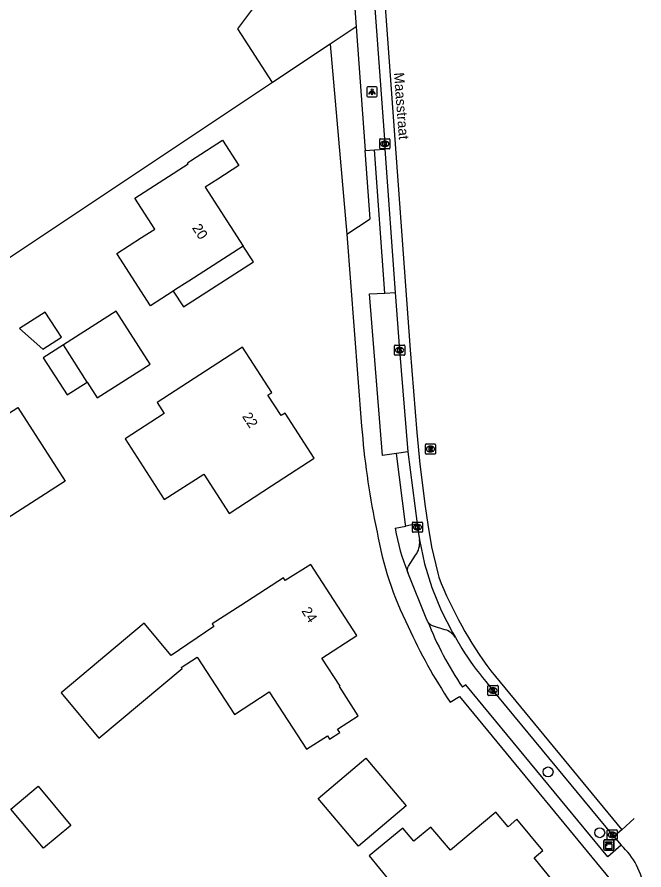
# Model space of a CAD drawing. Extents: x 156651 to 158072, y 387631 to 388990.
# Drawn here: x 157592.7 to 157654.4, y 387966 to 388049.9 of the extents above; entities that cross this region are included whole.
import ezdxf

# ---------------------------------------------------------------- set-up
doc = ezdxf.new("R2010")
doc.units = 0
for name, color, linetype in [('IMGEO_Boom', 7, 'Continuous'), ('IMGEO_Gemengd_bos', 7, 'Continuous'), ('IMGEO_Grasland_overig', 7, 'Continuous'), ('IMGEO_Kast', 7, 'Continuous'), ('IMGEO_Kolk', 7, 'Continuous'), ('IMGEO_Lichtpunt', 7, 'Continuous'), ('IMGEO_Openbare_ruimte_label', 7, 'Continuous'), ('IMGEO_Pand', 7, 'Continuous'), ('IMGEO_Pand_nummerreeks', 7, 'Continuous'), ('IMGEO_Pand_overbouw', 7, 'Continuous'), ('IMGEO_Pand_vergunning_verleend', 7, 'Continuous'), ('IMGEO_Rijbaan_lokaal_open', 7, 'Continuous'), ('IMGEO_Rioolput', 7, 'Continuous'), ('IMGEO_Voetpad_open', 7, 'Continuous')]:
    doc.layers.add(name, color=color, linetype=linetype)

msp = doc.modelspace()

# ---------------------------------------------------------------- linework, layer by layer
at = {"layer": 'IMGEO_Boom'}
for centre in [(157644.934, 387975.668), (157650.013, 387969.688)]:
    msp.add_circle(centre, 0.489, dxfattribs=at)
at = {"layer": 'IMGEO_Gemengd_bos'}
for points in [[(157617.824, 388043.477), (157568.335, 388010.487), (157551.976, 388000), (157551.233, 387999.524), (157548.86, 387998.003), (157547.263, 388000), (157521.408, 388032.33), (157543.243, 388052.841), (157602.721, 388107.759)], [(157617.824, 388043.477), (157614.435, 388048.767), (157619.655, 388055.738), (157620.91, 388056.517), (157620.87, 388061.577), (157622.996, 388063.579), (157624.989, 388063.89)], [(157626.073, 388048.976), (157623.5, 388047.261)], [(157623.5, 388047.261), (157617.824, 388043.477)]]:
    msp.add_lwpolyline(points, dxfattribs=at)
at = {"layer": 'IMGEO_Grasland_overig'}
msp.add_lwpolyline([(157623.5, 388047.261), (157625.156, 388028.557)], dxfattribs=at)
at = {"layer": 'IMGEO_Kast'}
for p, q in [((157650.416, 387968.061), (157650.416, 387968.902)), ((157650.416, 387968.902), (157650.416, 387968.061)), ((157650.491, 387968.986), (157651.332, 387968.986)), ((157651.332, 387968.986), (157650.491, 387968.986)), ((157651.416, 387968.911), (157651.416, 387968.07)), ((157651.416, 387968.07), (157651.416, 387968.911)), ((157651.341, 387967.986), (157650.5, 387967.986)), ((157650.5, 387967.986), (157651.341, 387967.986))]:
    msp.add_line(p, q, dxfattribs=at)
for points in [[(157650.611, 387968.776), (157651.211, 387968.776), (157651.211, 387968.691), (157650.611, 387968.691), (157650.611, 387968.776)], [(157650.611, 387968.601), (157651.211, 387968.601), (157651.211, 387968.112), (157650.611, 387968.112), (157650.611, 387968.601)]]:
    msp.add_lwpolyline(points, dxfattribs=at)
msp.add_circle((157650.695, 387968.45), 0.0377, dxfattribs=at)
for centre, start, end in [((157650.494, 387968.908), 92.4484, 184.28452), ((157650.494, 387968.908), 92.4484, 184.28452), ((157651.338, 387968.908), 2.4484, 94.28452), ((157651.338, 387968.908), 2.4484, 94.28452), ((157650.494, 387968.064), 182.4484, 274.28452), ((157650.494, 387968.064), 182.4484, 274.28452), ((157651.338, 387968.064), 272.4484, 4.28452), ((157651.338, 387968.064), 272.4484, 4.28452)]:
    msp.add_arc(centre, 0.0779, start, end, dxfattribs=at)
at = {"layer": 'IMGEO_Kolk'}
for p, q in [((157628.378, 388037.026), (157628.378, 388037.878)), ((157628.453, 388037.952), (157629.305, 388037.952)), ((157628.866, 388037.732), (157628.891, 388037.732)), ((157629.379, 388037.878), (157629.379, 388037.026)), ((157629.305, 388036.952), (157628.453, 388036.952)), ((157628.889, 388037.172), (157628.864, 388037.172)), ((157629.833, 388016.732), (157629.833, 388017.584)), ((157629.908, 388017.658), (157630.76, 388017.658)), ((157630.321, 388017.438), (157630.346, 388017.438)), ((157630.834, 388017.584), (157630.834, 388016.732)), ((157630.76, 388016.658), (157629.908, 388016.658)), ((157630.344, 388016.878), (157630.319, 388016.878)), ((157631.587, 387999.317), (157631.587, 388000.169)), ((157631.662, 388000.243), (157632.514, 388000.243)), ((157632.098, 387999.463), (157632.073, 387999.463)), ((157632.075, 388000.023), (157632.1, 388000.023)), ((157632.588, 388000.169), (157632.588, 387999.317)), ((157632.514, 387999.243), (157631.662, 387999.243)), ((157639.012, 387983.254), (157639.012, 387984.106)), ((157639.087, 387984.18), (157639.939, 387984.18)), ((157639.5, 387983.96), (157639.525, 387983.96)), ((157640.013, 387984.106), (157640.013, 387983.254)), ((157639.939, 387983.18), (157639.087, 387983.18)), ((157639.523, 387983.4), (157639.498, 387983.4)), ((157650.742, 387969.051), (157650.742, 387969.903)), ((157650.817, 387969.977), (157651.669, 387969.977)), ((157651.23, 387969.757), (157651.255, 387969.757)), ((157651.743, 387969.903), (157651.743, 387969.051)), ((157651.669, 387968.977), (157650.817, 387968.977)), ((157651.253, 387969.197), (157651.228, 387969.197))]:
    msp.add_line(p, q, dxfattribs=at)
for points in [[(157628.378, 388037.026), (157628.378, 388037.878)], [(157628.453, 388037.952), (157629.305, 388037.952)], [(157628.699, 388037.652), (157628.822, 388037.652), (157628.822, 388037.501), (157628.952, 388037.652), (157629.116, 388037.652), (157628.97, 388037.501), (157629.123, 388037.252), (157628.971, 388037.252), (157628.886, 388037.416), (157628.822, 388037.349), (157628.822, 388037.252), (157628.699, 388037.252), (157628.699, 388037.652)], [(157629.379, 388037.878), (157629.379, 388037.026)], [(157629.305, 388036.952), (157628.453, 388036.952)], [(157629.833, 388016.732), (157629.833, 388017.584)], [(157629.908, 388017.658), (157630.76, 388017.658)], [(157630.154, 388017.358), (157630.277, 388017.358), (157630.277, 388017.207), (157630.407, 388017.358), (157630.571, 388017.358), (157630.425, 388017.207), (157630.578, 388016.958), (157630.426, 388016.958), (157630.341, 388017.122), (157630.277, 388017.055), (157630.277, 388016.958), (157630.154, 388016.958), (157630.154, 388017.358)], [(157630.834, 388017.584), (157630.834, 388016.732)], [(157630.76, 388016.658), (157629.908, 388016.658)], [(157631.587, 387999.317), (157631.587, 388000.169)], [(157631.662, 388000.243), (157632.514, 388000.243)], [(157631.908, 387999.943), (157632.031, 387999.943), (157632.031, 387999.792), (157632.161, 387999.943), (157632.325, 387999.943), (157632.179, 387999.792), (157632.332, 387999.543), (157632.18, 387999.543), (157632.095, 387999.707), (157632.031, 387999.64), (157632.031, 387999.543), (157631.908, 387999.543), (157631.908, 387999.943)], [(157632.588, 388000.169), (157632.588, 387999.317)], [(157632.514, 387999.243), (157631.662, 387999.243)], [(157639.012, 387983.254), (157639.012, 387984.106)], [(157639.087, 387984.18), (157639.939, 387984.18)], [(157639.333, 387983.88), (157639.456, 387983.88), (157639.456, 387983.729), (157639.586, 387983.88), (157639.75, 387983.88), (157639.604, 387983.729), (157639.757, 387983.48), (157639.605, 387983.48), (157639.52, 387983.644), (157639.456, 387983.577), (157639.456, 387983.48), (157639.333, 387983.48), (157639.333, 387983.88)], [(157640.013, 387984.106), (157640.013, 387983.254)], [(157639.939, 387983.18), (157639.087, 387983.18)], [(157650.742, 387969.051), (157650.742, 387969.903)], [(157650.817, 387969.977), (157651.669, 387969.977)], [(157651.063, 387969.677), (157651.186, 387969.677), (157651.186, 387969.526), (157651.316, 387969.677), (157651.48, 387969.677), (157651.334, 387969.526), (157651.487, 387969.277), (157651.335, 387969.277), (157651.25, 387969.441), (157651.186, 387969.374), (157651.186, 387969.277), (157651.063, 387969.277), (157651.063, 387969.677)], [(157651.743, 387969.903), (157651.743, 387969.051)], [(157651.669, 387968.977), (157650.817, 387968.977)]]:
    msp.add_lwpolyline(points, dxfattribs=at)
for centre, start, end in [((157628.455, 388037.876), 91.55205, 178.44795), ((157628.455, 388037.876), 91.55205, 178.44795), ((157629.303, 388037.876), 1.55205, 88.44795), ((157629.303, 388037.876), 1.55205, 88.44795), ((157628.455, 388037.028), 181.55205, 268.44795), ((157628.455, 388037.028), 181.55205, 268.44795), ((157629.303, 388037.028), 271.55205, 358.44795), ((157629.303, 388037.028), 271.55205, 358.44795), ((157629.91, 388017.582), 91.55205, 178.44795), ((157629.91, 388017.582), 91.55205, 178.44795), ((157630.758, 388017.582), 1.55205, 88.44795), ((157630.758, 388017.582), 1.55205, 88.44795), ((157629.91, 388016.734), 181.55205, 268.44795), ((157629.91, 388016.734), 181.55205, 268.44795), ((157630.758, 388016.734), 271.55205, 358.44795), ((157630.758, 388016.734), 271.55205, 358.44795), ((157631.664, 388000.167), 91.55205, 178.44795), ((157631.664, 388000.167), 91.55205, 178.44795), ((157632.512, 388000.167), 1.55205, 88.44795), ((157632.512, 388000.167), 1.55205, 88.44795), ((157631.664, 387999.319), 181.55205, 268.44795), ((157631.664, 387999.319), 181.55205, 268.44795), ((157632.512, 387999.319), 271.55205, 358.44795), ((157632.512, 387999.319), 271.55205, 358.44795), ((157639.089, 387984.104), 91.55205, 178.44795), ((157639.089, 387984.104), 91.55205, 178.44795), ((157639.937, 387984.104), 1.55205, 88.44795), ((157639.937, 387984.104), 1.55205, 88.44795), ((157639.089, 387983.256), 181.55205, 268.44795), ((157639.089, 387983.256), 181.55205, 268.44795), ((157639.937, 387983.256), 271.55205, 358.44795), ((157639.937, 387983.256), 271.55205, 358.44795), ((157650.819, 387969.901), 91.55205, 178.44795), ((157650.819, 387969.901), 91.55205, 178.44795), ((157651.667, 387969.901), 1.55205, 88.44795), ((157651.667, 387969.901), 1.55205, 88.44795), ((157650.819, 387969.053), 181.55205, 268.44795), ((157650.819, 387969.053), 181.55205, 268.44795), ((157651.667, 387969.053), 271.55205, 358.44795), ((157651.667, 387969.053), 271.55205, 358.44795)]:
    msp.add_arc(centre, 0.0765, start, end, dxfattribs=at)
for centre, major_axis, ratio, start_param, end_param in [((157628.865, 388037.452), (-0.387, 0.002), 0.722429, 4.712389, 7.853982), ((157628.89, 388037.452), (-0.39, 0.002), 0.717154, 1.570796, 4.712389), ((157630.32, 388017.158), (-0.387, 0.002), 0.722429, 4.712389, 7.853982), ((157630.345, 388017.158), (-0.39, 0.002), 0.717154, 1.570796, 4.712389), ((157632.074, 387999.743), (-0.387, 0.002), 0.722429, 4.712389, 7.853982), ((157632.099, 387999.743), (-0.39, 0.002), 0.717154, 1.570796, 4.712389), ((157639.499, 387983.68), (-0.387, 0.002), 0.722429, 4.712389, 7.853982), ((157639.524, 387983.68), (-0.39, 0.002), 0.717154, 1.570796, 4.712389), ((157651.229, 387969.477), (-0.387, 0.002), 0.722429, 4.712389, 7.853982), ((157651.254, 387969.477), (-0.39, 0.002), 0.717154, 1.570796, 4.712389)]:
    msp.add_ellipse(centre, major_axis=major_axis, ratio=ratio, start_param=start_param, end_param=end_param, dxfattribs=at)
at = {"layer": 'IMGEO_Lichtpunt'}
for p, q in [((157628.028, 388043.068), (157627.22, 388043.068)), ((157628.028, 388043.068), (157627.22, 388043.068)), ((157627.126, 388042.973), (157627.126, 388042.166)), ((157627.126, 388042.973), (157627.126, 388042.166)), ((157628.122, 388042.166), (157628.122, 388042.973)), ((157628.122, 388042.166), (157628.122, 388042.973)), ((157627.22, 388042.072), (157628.028, 388042.072)), ((157627.22, 388042.072), (157628.028, 388042.072))]:
    msp.add_line(p, q, dxfattribs=at)
for points in [[(157627.5, 388042.637), (157627.539, 388042.609), (157627.351, 388042.347), (157627.313, 388042.374), (157627.5, 388042.637)], [(157627.602, 388042.589), (157627.649, 388042.589), (157627.649, 388042.267), (157627.602, 388042.267), (157627.602, 388042.589)], [(157627.712, 388042.609), (157627.75, 388042.636), (157627.937, 388042.374), (157627.898, 388042.346), (157627.712, 388042.609)]]:
    msp.add_lwpolyline(points, dxfattribs=at)
msp.add_circle((157627.625, 388042.771), 0.0994, dxfattribs=at)
for centre, start, end in [((157627.22, 388042.973), 90, 180), ((157627.22, 388042.973), 90, 180), ((157628.028, 388042.973), 0, 90), ((157628.028, 388042.973), 0, 90), ((157627.22, 388042.166), 180, 270), ((157627.22, 388042.166), 180, 270), ((157628.028, 388042.166), 270, 0), ((157628.028, 388042.166), 270, 360)]:
    msp.add_arc(centre, 0.0946, start, end, dxfattribs=at)
at = {"layer": 'IMGEO_Pand'}
for points in [[(157604.284, 388032.105), (157609.559, 388035.494), (157609.494, 388035.595), (157609.757, 388035.764), (157612.929, 388037.803), (157614.538, 388035.305), (157612.468, 388033.969), (157611.21, 388033.173), (157614.967, 388027.387), (157609.606, 388023.95), (157609.43, 388023.837), (157608.307, 388023.117), (157608.078, 388022.97), (157605.825, 388021.526), (157602.528, 388026.67), (157604.969, 388028.235), (157606.267, 388029.067), (157604.284, 388032.105)], [(157592.949, 388019.276), (157595.262, 388017.262), (157597.081, 388018.423), (157595.497, 388020.903), (157592.949, 388019.276)], [(157599.613, 388014.012), (157600.601, 388012.466), (157605.791, 388015.78), (157602.464, 388020.988), (157597.275, 388017.674)], [(157597.275, 388017.674), (157595.296, 388016.41), (157597.635, 388012.749), (157599.613, 388014.012)], [(157599.613, 388014.012), (157597.275, 388017.674)], [(157613.565, 388001.104), (157617.741, 388003.806), (157621.939, 388006.521), (157619.068, 388010.973), (157618.673, 388010.718), (157617.367, 388012.738), (157617.762, 388012.993), (157614.891, 388017.439), (157610.693, 388014.724), (157606.487, 388012.003), (157607.194, 388010.912), (157603.348, 388008.424), (157607.189, 388002.474), (157611.072, 388004.959), (157613.565, 388001.104)], [(157589.978, 388000), (157585.564, 388006.896), (157592.807, 388011.532), (157597.454, 388004.272), (157590.78, 388000), (157590.211, 387999.636), (157589.978, 388000)], [(157626.116, 387989.074), (157621.591, 387996.086), (157619.089, 387994.488), (157618.916, 387994.757), (157614.716, 387992.045), (157611.901, 387990.227), (157612.074, 387989.958), (157607.88, 387987.117), (157605.211, 387990.296), (157597.04, 387983.45), (157600.771, 387978.996), (157608.942, 387985.842), (157608.852, 387985.95), (157610.44, 387986.951), (157614.098, 387981.313), (157617.52, 387983.535), (157621.18, 387977.899), (157623.233, 387979.224), (157623.449, 387978.888), (157624.454, 387979.536), (157624.237, 387979.872), (157626.275, 387981.188), (157624.424, 387984.056), (157624.487, 387984.097), (157622.698, 387986.868), (157626.116, 387989.074)], [(157594.801, 387974.265), (157598.01, 387970.414), (157595.316, 387968.168), (157592.107, 387972.019), (157594.801, 387974.265)], [(157641.855, 387971.008), (157641.001, 387970.283), (157639.782, 387971.718), (157635.327, 387967.986), (157633.419, 387970.249), (157631.727, 387968.846), (157630.652, 387970.127), (157627.336, 387967.407), (157633.43, 387959.935), (157636.9, 387962.84), (157637.544, 387962.071), (157637.193, 387961.773), (157638.755, 387959.934), (157639.092, 387960.23), (157641.072, 387957.862), (157642.829, 387959.338), (157643.558, 387958.481), (157647.631, 387961.869), (157645.199, 387964.783), (157645.409, 387964.97), (157643.558, 387967.211), (157644.417, 387967.948), (157641.855, 387971.008)]]:
    msp.add_lwpolyline(points, dxfattribs=at)
at = {"layer": 'IMGEO_Pand_overbouw'}
msp.add_lwpolyline([(157615.973, 388025.838), (157614.967, 388027.387), (157609.606, 388023.95), (157609.43, 388023.837), (157608.307, 388023.117), (157608.078, 388022.97), (157609.075, 388021.416)], close=True, dxfattribs=at)
at = {"layer": 'IMGEO_Pand_vergunning_verleend'}
msp.add_lwpolyline([(157627.012, 387977.023), (157630.978, 387972.336), (157626.29, 387968.369), (157622.324, 387973.057), (157627.012, 387977.023)], dxfattribs=at)
at = {"layer": 'IMGEO_Rijbaan_lokaal_open'}
for points in [[(157625.617, 388082.408), (157625.649, 388082.108), (157625.747, 388080.633), (157627.187, 388060.606), (157628.878, 388037.453), (157628.892, 388036.942)], [(157626.67, 388082.386), (157626.673, 388082.152), (157628.231, 388060.388), (157631.368, 388017.187), (157632.02, 388009.07), (157632.319, 388005.936), (157632.839, 388001.765), (157633.123, 388000), (157633.473, 387997.823), (157634.096, 387995.205), (157634.191, 387994.819)], [(157628.892, 388036.942), (157629.909, 388022.812)], [(157629.909, 388022.812), (157630.335, 388017.158), (157631.131, 388007.154)], [(157631.131, 388007.154), (157632.046, 388000.076)], [(157632.046, 388000.076), (157632.089, 387999.743), (157632.294, 387998.512)], [(157632.294, 387998.512), (157632.794, 387996.132), (157633.504, 387993.806), (157634.419, 387991.553), (157635.532, 387989.39), (157635.815, 387988.907)], [(157635.815, 387988.907), (157636.464, 387987.804)], [(157639.292, 387985.616), (157652.191, 387969.963)], [(157638.802, 387984.554), (157639.513, 387983.68), (157651.244, 387969.477), (157651.402, 387969.32)], [(157653.402, 387971.074), (157652.191, 387969.963)], [(157652.191, 387969.963), (157651.402, 387969.32)], [(157651.402, 387969.32), (157652.109, 387968.454)]]:
    msp.add_lwpolyline(points, dxfattribs=at)
for centre, radius, start, end in [((157671.371, 388009.412), 39.941, 201.4295, 216.56758), ((157661.522, 388003.364), 29.496, 211.83917, 219.62215), ((157647.546, 387963.337), 6.856, 6.32865, 48.27385)]:
    msp.add_arc(centre, radius, start, end, dxfattribs=at)
at = {"layer": 'IMGEO_Rioolput'}
for p, q in [((157632.866, 388007.004), (157632.866, 388007.856)), ((157632.941, 388007.93), (157633.793, 388007.93)), ((157633.867, 388007.856), (157633.867, 388007.004)), ((157633.377, 388007.15), (157633.352, 388007.15)), ((157633.354, 388007.71), (157633.379, 388007.71)), ((157633.793, 388006.93), (157632.941, 388006.93))]:
    msp.add_line(p, q, dxfattribs=at)
for points in [[(157632.866, 388007.004), (157632.866, 388007.856)], [(157632.941, 388007.93), (157633.793, 388007.93)], [(157633.867, 388007.856), (157633.867, 388007.004)], [(157633.455, 388007.628), (157633.203, 388007.63), (157633.203, 388007.23)], [(157633.203, 388007.23), (157633.327, 388007.23), (157633.327, 388007.392), (157633.338, 388007.392)], [(157633.381, 388007.549), (157633.327, 388007.549), (157633.327, 388007.468)], [(157633.327, 388007.468), (157633.379, 388007.468)], [(157633.385, 388007.363), (157633.456, 388007.23), (157633.596, 388007.23), (157633.531, 388007.356)], [(157633.793, 388006.93), (157632.941, 388006.93)]]:
    msp.add_lwpolyline(points, dxfattribs=at)
for centre, radius, start, end in [((157632.943, 388007.854), 0.0765, 91.55205, 178.44795), ((157632.943, 388007.854), 0.0765, 91.55205, 178.44795), ((157633.791, 388007.854), 0.0765, 1.55205, 88.44795), ((157633.791, 388007.854), 0.0765, 1.55205, 88.44795), ((157632.943, 388007.006), 0.0765, 181.55205, 268.44795), ((157632.943, 388007.006), 0.0765, 181.55205, 268.44795), ((157633.337, 388007.339), 0.0533, 26.02933, 88.69889), ((157633.363, 388007.657), 0.19, 274.7715, 282.96867), ((157633.387, 388007.453), 0.0964, 77.00612, 93.18647), ((157633.401, 388007.51), 0.0378, 276.66336, 79.67722), ((157633.454, 388007.518), 0.109, 350.36119, 89.41601), ((157633.452, 388007.518), 0.112, 277.58423, 350.98172), ((157633.436, 388007.303), 0.108, 29.51342, 73.79051), ((157633.791, 388007.006), 0.0765, 271.55205, 358.44795), ((157633.791, 388007.006), 0.0765, 271.55205, 358.44795)]:
    msp.add_arc(centre, radius, start, end, dxfattribs=at)
for centre, major_axis, ratio, start_param, end_param in [((157633.353, 388007.43), (-0.387, 0.002), 0.722429, 4.712389, 7.853982), ((157633.378, 388007.43), (-0.39, 0.002), 0.717154, 1.570796, 4.712389)]:
    msp.add_ellipse(centre, major_axis=major_axis, ratio=ratio, start_param=start_param, end_param=end_param, dxfattribs=at)
at = {"layer": 'IMGEO_Voetpad_open'}
for points in [[(157624.989, 388063.89), (157625.236, 388060.439), (157626.073, 388048.976)], [(157626.073, 388048.976), (157626.962, 388036.8)], [(157625.156, 388028.557), (157627.454, 388030.067), (157626.962, 388036.8)], [(157626.962, 388036.8), (157627.871, 388036.867)], [(157627.871, 388036.867), (157628.892, 388036.942)], [(157628.887, 388022.764), (157627.871, 388036.867)], [(157625.156, 388028.557), (157626.602, 388009.687)], [(157630.041, 388006.991), (157628.663, 388006.804), (157627.39, 388022.685), (157628.887, 388022.764)], [(157628.887, 388022.764), (157629.909, 388022.812)], [(157631.131, 388007.154), (157630.041, 388006.991)], [(157630.949, 387999.834), (157630.928, 388000), (157630.041, 388006.991)], [(157627.966, 388000), (157628.121, 387999.267)], [(157629.884, 387999.636), (157630.949, 387999.834)], [(157632.046, 388000.076), (157631.701, 388000), (157630.949, 387999.834)], [(157631.14, 387995.271), (157631.137, 387995.283), (157631.121, 387995.352), (157631.112, 387995.422), (157631.108, 387995.493), (157631.112, 387995.564), (157631.121, 387995.634), (157631.137, 387995.704), (157631.159, 387995.771), (157631.186, 387995.836), (157631.22, 387995.899), (157631.911, 387996.995), (157632.015, 387997.154), (157632.105, 387997.322), (157632.179, 387997.497), (157632.237, 387997.679), (157632.279, 387997.864), (157632.304, 387998.053), (157632.312, 387998.243), (157632.303, 387998.433), (157632.294, 387998.512)], [(157633.09, 387990.489), (157632.951, 387990.791), (157631.195, 387995.133), (157631.14, 387995.271)], [(157635.815, 387988.907), (157635.724, 387989.036), (157635.621, 387989.156), (157635.509, 387989.267), (157635.387, 387989.367), (157635.256, 387989.456), (157635.118, 387989.532), (157634.974, 387989.597), (157634.825, 387989.648), (157634.791, 387989.657), (157633.669, 387989.991), (157633.658, 387989.994), (157633.578, 387990.025), (157633.5, 387990.062), (157633.426, 387990.106), (157633.357, 387990.156), (157633.292, 387990.213), (157633.232, 387990.275), (157633.179, 387990.342), (157633.131, 387990.413), (157633.09, 387990.489)], [(157652.109, 387968.454), (157650.801, 387967.303), (157636.858, 387984.227), (157636.525, 387983.991)], [(157635.307, 387982.52), (157636.218, 387983.074), (157652.9, 387962.822)]]:
    msp.add_lwpolyline(points, dxfattribs=at)
for centre, radius, start, end in [((157703.387, 388015.559), 77.009, 184.37334, 191.6566), ((157652.487, 388003.777), 22.979, 190.38104, 201.72461), ((157661.334, 388005.048), 33.713, 189.87429, 206.5661), ((157664.114, 388002.732), 33.352, 201.53589, 214.18814), ((157677.979, 388011.018), 51.313, 204.215, 213.73608)]:
    msp.add_arc(centre, radius, start, end, dxfattribs=at)

# ---------------------------------------------------------------- texts
at = {"layer": 'IMGEO_Openbare_ruimte_label'}
msp.add_text('Maasstraat', height=1, rotation=274.35915, dxfattribs=at).set_placement((157629.771, 388044.436))
at = {"layer": 'IMGEO_Pand_nummerreeks'}
for s, rotation, p in [('20', 302.99643, (157609.889, 388029.185)), ('22', 302.88407, (157614.816, 388010.643)), ('24', 302.836, (157620.65, 387991.496))]:
    msp.add_text(s, height=1, rotation=rotation, dxfattribs=at).set_placement(p)

doc.saveas('drawing.dxf')
